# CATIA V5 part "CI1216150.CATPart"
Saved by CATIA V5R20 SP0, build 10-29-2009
Part number: CI1216150
Bounding box of the stored display mesh (mm): x -15 to 15, y -11.764 to 174, z -17.351 to 17.399
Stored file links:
  C:\Users\Raffaele\Desktop\3D X SITO CF\BOLEX\19-INCLINED ASSEMBLY REF_CI\CI1216150.CATPart

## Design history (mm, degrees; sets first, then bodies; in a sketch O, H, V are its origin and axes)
Set1
  DatumSurface1 to DatumSurface16 "MANIFOLD_SOLID_BREP #385"
  DatumSurface17 to DatumSurface39 "MANIFOLD_SOLID_BREP #1110"
Body1 (main body)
